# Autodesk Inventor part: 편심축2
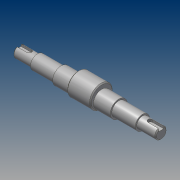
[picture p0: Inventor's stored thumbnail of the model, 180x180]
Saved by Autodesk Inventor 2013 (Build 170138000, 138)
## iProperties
Created: 2014-12
Part Number: 편심축2
Material: Generic
Document SubType Name: Modeling
Designer: CAD-B13
Density: 1 g/cm^3
Author: CAD-B13
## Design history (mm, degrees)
sketch "스케치1"
  geometry: L1 (-75.5, 0)-(75.5, 0); L2 (-75.5, 0)-(-75.5, 6); L3 (-75.5, 6)-(-55.5, 6); L4 (-55.5, 6)-(-55.5, 7.5); L5 (-55.5, 7.5)-(-30.5, 7.5); L6 (-30.5, 7.5)-(-30.5, 9); L7 (-30.5, 9)-(-12.5, 9); L8 (12.5, 9)-(30.5, 9); L9 (30.5, 9)-(30.5, 7.5); L10 (30.5, 7.5)-(55.5, 7.5); L11 (55.5, 7.5)-(55.5, 6); L12 (55.5, 6)-(75.5, 6); L13 (75.5, 6)-(75.5, 0); L14 (-12.5, 2)-(11.388, 2); L15 (-12.5, 2)-(12.5, 2); L16 (12.5, 2)-(12.5, 14); L17 (12.5, 14)-(-12.5, 14); L18 (-12.5, 14)-(-12.5, 2); L19 (-12.5, 9)-(12.5, 9); 2 further points
  constraints: 38 end point, 8 parallel, 4 perpendicular, 2 horizontal, 1 coincident, 1 midpoint
  dimensions: "d3" = 12 diameter of L3 L1; "d4" = 15 diameter of L5 L1; "d5" = 18 diameter of L7 L1; "d6" = 151 distance of L1.start L1.end; "d7" = 12 diameter of L12 L1; "d8" = 15 diameter of L10 L1; "d9" = 18 diameter of L8 L1; "d10" = 20 distance of L11.end L12.end; "d11" = 25 distance of L9.end L10.end; "d13" = 20 distance of L2.end L3.end; "d14" = 25 distance of L4.end L5.end; "d24" = 2 distance from line of L1.end L14; "d25" = 24 diameter of L17 L15; "d26" = 18 distance between parallel lines of L18 L6; "d27" = 18 distance between parallel lines of L9 L16; "d28" = 25 distance between parallel lines of L16 L18; "d29" = 2 distance between parallel lines of L1 L14 (derived)
revolve "회전1" stored, may be unused: angle "d16" = 90 deg
revolve "회전2" stored, may be unused: angle "d30" = 90 deg
sketch "스케치3"
  geometry: L1 (-75.5, 6)-(-55.5, 6) reference; L2 (-75.5, -6)-(-75.5, 6) reference; L3 (-61.5, 6)-(-61.5, 3); L4 (-61.5, 3)-(-75.5, 3); L5 (75.5, -6)-(75.5, 6) reference; L6 (55.5, 6)-(75.5, 6) reference; L7 (61.5, 6)-(61.5, 3); L8 (61.5, 3)-(75.5, 3); 1 further point
  constraints: 8 end point, 4 point on line
  dimensions: "d31" = 3 distance between parallel lines of L1 L4; "d32" = 14 distance between parallel lines of L3 L2; "d33" = 3 distance between parallel lines of L6 L8; "d34" = 14 distance between parallel lines of L7 L5
extrude "돌출2" cut sketch "스케치3" stored distance "d35" = 5; taper "d36" = 0 deg
fillet "모깎기2" dims "d37" = 2.5
chamfer "모따기1" distance "d38" = 1; stored, may be unused: second distance "d39" = 2, angle "d40" = 45 deg
node "솔리드1"
